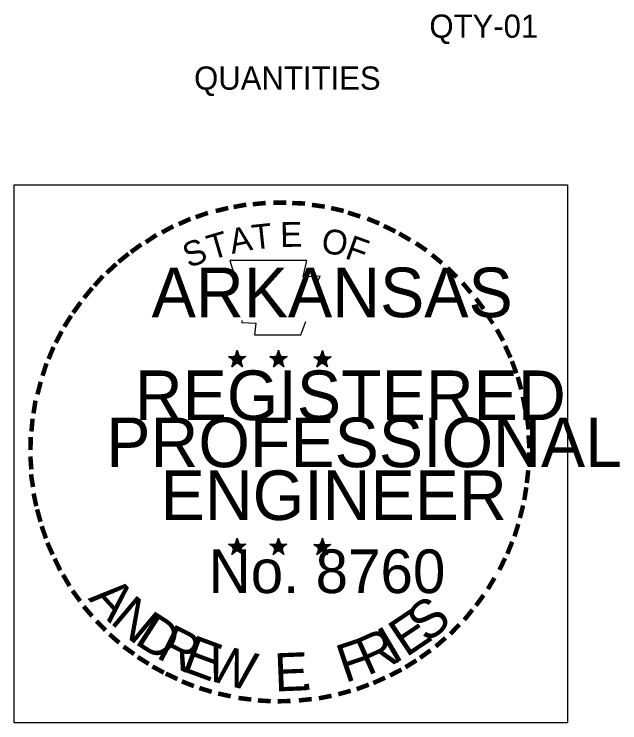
# Model space of a CAD drawing. Extents: x 1225909 to 1228704, y 151309 to 152305.
# Drawn here: x 1227979.2 to 1228131.9, y 152126.8 to 152305.5 of the extents above; entities that cross this region are included whole.
import ezdxf

# ---------------------------------------------------------------- set-up
doc = ezdxf.new("R2010")
doc.units = 0
for name, color, linetype in [('R_Border', 7, 'Continuous'), ('R_Border PE', 7, 'Continuous'), ('R_Border Prem', 7, 'Continuous')]:
    doc.layers.add(name, color=color, linetype=linetype)

msp = doc.modelspace()

# ---------------------------------------------------------------- linework, layer by layer
at = {"layer": 'R_Border PE'}
for p, q in [((1228035.41, 152220.8), (1228035.1, 152219.23)), ((1228035.41, 152220.8), (1228035.16, 152219.17)), ((1228035.41, 152220.8), (1228035.35, 152219.23)), ((1228035.41, 152218.48), (1228035.41, 152220.8)), ((1228035.41, 152220.8), (1228035.85, 152219.17)), ((1228035.41, 152220.8), (1228035.72, 152219.23)), ((1228035.41, 152220.8), (1228035.6, 152219.23)), ((1228045.85, 152220.8), (1228045.54, 152219.23)), ((1228045.85, 152220.8), (1228045.6, 152219.17)), ((1228045.85, 152220.8), (1228045.72, 152219.23)), ((1228045.85, 152218.48), (1228045.85, 152220.8)), ((1228045.85, 152220.8), (1228046.29, 152219.17)), ((1228045.85, 152220.8), (1228046.16, 152219.23)), ((1228045.85, 152220.8), (1228045.97, 152219.23)), ((1228056.91, 152220.67), (1228056.54, 152219.17)), ((1228056.91, 152220.67), (1228056.66, 152219.11)), ((1228056.91, 152220.67), (1228056.79, 152219.11)), ((1228056.91, 152218.42), (1228056.91, 152220.67)), ((1228056.91, 152220.67), (1228057.35, 152219.11)), ((1228056.91, 152220.67), (1228057.22, 152219.11)), ((1228056.91, 152220.67), (1228057.04, 152219.17)), ((1228033.22, 152219.17), (1228035.41, 152218.48)), ((1228033.22, 152219.17), (1228034.85, 152219.05)), ((1228033.22, 152219.17), (1228034.85, 152218.92)), ((1228033.22, 152219.17), (1228034.79, 152218.8)), ((1228033.22, 152219.17), (1228034.79, 152218.55)), ((1228033.22, 152219.17), (1228034.72, 152218.42)), ((1228033.22, 152219.17), (1228034.72, 152218.3)), ((1228037.6, 152219.17), (1228035.41, 152218.48)), ((1228037.6, 152219.17), (1228035.66, 152219.05)), ((1228037.6, 152219.17), (1228035.79, 152218.86)), ((1228037.6, 152219.17), (1228035.79, 152218.73)), ((1228037.6, 152219.17), (1228036.22, 152218.61)), ((1228037.6, 152219.17), (1228036.35, 152218.55)), ((1228037.6, 152219.17), (1228036.41, 152218.48)), ((1228043.66, 152219.17), (1228045.85, 152218.48)), ((1228043.66, 152219.17), (1228045.29, 152219.05)), ((1228043.66, 152219.17), (1228045.29, 152218.92)), ((1228043.66, 152219.17), (1228045.22, 152218.8)), ((1228043.66, 152219.17), (1228045.16, 152218.55)), ((1228043.66, 152219.17), (1228045.16, 152218.42)), ((1228043.66, 152219.17), (1228045.16, 152218.3)), ((1228048.04, 152219.17), (1228045.85, 152218.48)), ((1228048.04, 152219.17), (1228046.1, 152219.05)), ((1228048.04, 152219.17), (1228046.22, 152218.86)), ((1228048.04, 152219.17), (1228046.22, 152218.73)), ((1228048.04, 152219.17), (1228046.66, 152218.61)), ((1228048.04, 152219.17), (1228046.79, 152218.55)), ((1228048.04, 152219.17), (1228046.85, 152218.48)), ((1228054.72, 152219.11), (1228056.91, 152218.42)), ((1228054.72, 152219.11), (1228056.35, 152218.92)), ((1228054.72, 152219.11), (1228056.29, 152218.8)), ((1228054.72, 152219.11), (1228056.29, 152218.73)), ((1228054.72, 152219.11), (1228056.22, 152218.48)), ((1228054.72, 152219.11), (1228056.22, 152218.36)), ((1228054.72, 152219.11), (1228056.22, 152218.23)), ((1228059.1, 152219.11), (1228056.91, 152218.42)), ((1228059.1, 152219.11), (1228057.16, 152218.98)), ((1228059.1, 152219.11), (1228057.29, 152218.8)), ((1228059.1, 152219.11), (1228057.29, 152218.67)), ((1228059.1, 152219.11), (1228057.72, 152218.55)), ((1228059.1, 152219.11), (1228057.79, 152218.48)), ((1228059.1, 152219.11), (1228057.91, 152218.42)), ((1228034.1, 152216.61), (1228035.41, 152218.48)), ((1228034.1, 152216.61), (1228034.79, 152218.36)), ((1228034.1, 152216.61), (1228034.85, 152218.17)), ((1228034.1, 152216.61), (1228034.97, 152218.11)), ((1228034.1, 152216.61), (1228035.41, 152217.98)), ((1228034.1, 152216.61), (1228035.16, 152217.92)), ((1228034.1, 152216.61), (1228035.47, 152217.8)), ((1228036.79, 152216.61), (1228035.41, 152218.48)), ((1228036.79, 152216.61), (1228035.41, 152217.98)), ((1228036.79, 152216.61), (1228035.41, 152217.8)), ((1228036.79, 152216.61), (1228035.66, 152217.92)), ((1228036.79, 152216.61), (1228035.85, 152218.17)), ((1228036.79, 152216.61), (1228035.91, 152218.42)), ((1228036.79, 152216.61), (1228036.04, 152218.48)), ((1228044.54, 152216.61), (1228045.85, 152218.48)), ((1228044.54, 152216.61), (1228045.22, 152218.36)), ((1228044.54, 152216.61), (1228045.29, 152218.17)), ((1228044.54, 152216.61), (1228045.41, 152218.11)), ((1228044.54, 152216.61), (1228045.85, 152217.98)), ((1228044.54, 152216.61), (1228045.6, 152217.92)), ((1228044.54, 152216.61), (1228045.91, 152217.8)), ((1228047.22, 152216.61), (1228045.85, 152218.48)), ((1228047.22, 152216.61), (1228045.85, 152217.98)), ((1228047.22, 152216.61), (1228045.85, 152217.8)), ((1228047.22, 152216.61), (1228046.1, 152217.92)), ((1228047.22, 152216.61), (1228046.29, 152218.17)), ((1228047.22, 152216.61), (1228046.35, 152218.42)), ((1228047.22, 152216.61), (1228046.47, 152218.48)), ((1228055.54, 152216.55), (1228056.91, 152218.42)), ((1228055.54, 152216.55), (1228056.29, 152218.3)), ((1228055.54, 152216.55), (1228056.35, 152218.11)), ((1228055.54, 152216.55), (1228056.47, 152218.05)), ((1228055.54, 152216.55), (1228056.91, 152217.92)), ((1228055.54, 152216.55), (1228056.66, 152217.86)), ((1228055.54, 152216.55), (1228056.97, 152217.73)), ((1228058.22, 152216.55), (1228056.91, 152218.42)), ((1228058.22, 152216.55), (1228056.91, 152217.92)), ((1228058.22, 152216.55), (1228056.91, 152217.73)), ((1228058.22, 152216.55), (1228057.16, 152217.86)), ((1228058.22, 152216.55), (1228057.35, 152218.11)), ((1228058.22, 152216.55), (1228057.41, 152218.36)), ((1228058.22, 152216.55), (1228057.54, 152218.36)), ((1228035.41, 152173.42), (1228035.04, 152171.92)), ((1228035.41, 152173.42), (1228035.16, 152171.86)), ((1228035.41, 152173.42), (1228035.29, 152171.86)), ((1228035.41, 152171.17), (1228035.41, 152173.42)), ((1228035.41, 152173.42), (1228035.85, 152171.86)), ((1228035.41, 152173.42), (1228035.72, 152171.86)), ((1228035.41, 152173.42), (1228035.54, 152171.86)), ((1228045.85, 152173.42), (1228045.47, 152171.92)), ((1228045.85, 152173.42), (1228045.6, 152171.86)), ((1228045.85, 152173.42), (1228045.72, 152171.86)), ((1228045.85, 152171.17), (1228045.85, 152173.42)), ((1228045.85, 152173.42), (1228046.22, 152171.86)), ((1228045.85, 152173.42), (1228046.16, 152171.86)), ((1228045.85, 152173.42), (1228045.97, 152171.86)), ((1228056.91, 152173.36), (1228056.54, 152171.8)), ((1228056.91, 152173.36), (1228056.66, 152171.8)), ((1228056.91, 152173.36), (1228056.79, 152171.8)), ((1228056.91, 152171.11), (1228056.91, 152173.36)), ((1228056.91, 152173.36), (1228057.29, 152171.8)), ((1228056.91, 152173.36), (1228057.22, 152171.8)), ((1228056.91, 152173.36), (1228057.04, 152171.8)), ((1228033.22, 152171.86), (1228035.41, 152171.17)), ((1228033.22, 152171.86), (1228034.85, 152171.67)), ((1228033.22, 152171.86), (1228034.79, 152171.55)), ((1228033.22, 152171.86), (1228034.79, 152171.48)), ((1228033.22, 152171.86), (1228034.72, 152171.23)), ((1228033.22, 152171.86), (1228034.72, 152171.11)), ((1228033.22, 152171.86), (1228034.72, 152170.98)), ((1228034.04, 152169.3), (1228035.41, 152171.17)), ((1228034.04, 152169.3), (1228034.79, 152171.05)), ((1228034.04, 152169.3), (1228034.85, 152170.8)), ((1228034.04, 152169.3), (1228034.97, 152170.73)), ((1228034.04, 152169.3), (1228035.41, 152170.67)), ((1228034.04, 152169.3), (1228035.16, 152170.61)), ((1228034.04, 152169.3), (1228035.41, 152170.48)), ((1228036.72, 152169.3), (1228035.35, 152170.48)), ((1228037.6, 152171.86), (1228035.41, 152171.17)), ((1228036.72, 152169.3), (1228035.41, 152171.17)), ((1228036.72, 152169.3), (1228035.41, 152170.61)), ((1228036.72, 152169.3), (1228035.6, 152170.61)), ((1228037.6, 152171.86), (1228035.66, 152171.73)), ((1228037.6, 152171.86), (1228035.79, 152171.55)), ((1228037.6, 152171.86), (1228035.79, 152171.42)), ((1228036.72, 152169.3), (1228035.85, 152171.11)), ((1228036.72, 152169.3), (1228035.85, 152170.86)), ((1228036.72, 152169.3), (1228036.04, 152171.11)), ((1228037.6, 152171.86), (1228036.16, 152171.3)), ((1228037.6, 152171.86), (1228036.29, 152171.23)), ((1228037.6, 152171.86), (1228036.41, 152171.11)), ((1228043.66, 152171.86), (1228045.85, 152171.17)), ((1228043.66, 152171.86), (1228045.22, 152171.67)), ((1228043.66, 152171.86), (1228045.22, 152171.55)), ((1228043.66, 152171.86), (1228045.22, 152171.48)), ((1228043.66, 152171.86), (1228045.16, 152171.23)), ((1228043.66, 152171.86), (1228045.16, 152171.11)), ((1228043.66, 152171.86), (1228045.16, 152170.98)), ((1228044.47, 152169.3), (1228045.85, 152171.17)), ((1228044.47, 152169.3), (1228045.22, 152171.05)), ((1228044.47, 152169.3), (1228045.29, 152170.8)), ((1228044.47, 152169.3), (1228045.41, 152170.73)), ((1228044.47, 152169.3), (1228045.85, 152170.67)), ((1228044.47, 152169.3), (1228045.6, 152170.61)), ((1228044.47, 152169.3), (1228045.85, 152170.48)), ((1228047.16, 152169.3), (1228045.79, 152170.48)), ((1228047.97, 152171.86), (1228045.85, 152171.17)), ((1228047.16, 152169.3), (1228045.85, 152171.17)), ((1228047.16, 152169.3), (1228045.85, 152170.61)), ((1228047.16, 152169.3), (1228046.04, 152170.61)), ((1228047.97, 152171.86), (1228046.1, 152171.73)), ((1228047.97, 152171.86), (1228046.22, 152171.55)), ((1228047.97, 152171.86), (1228046.22, 152171.42)), ((1228047.16, 152169.3), (1228046.29, 152171.11)), ((1228047.16, 152169.3), (1228046.29, 152170.86)), ((1228047.16, 152169.3), (1228046.47, 152171.11)), ((1228047.97, 152171.86), (1228046.6, 152171.3)), ((1228047.97, 152171.86), (1228046.72, 152171.23)), ((1228047.97, 152171.86), (1228046.85, 152171.11)), ((1228054.72, 152171.8), (1228056.91, 152171.11)), ((1228054.72, 152171.8), (1228056.29, 152171.61)), ((1228054.72, 152171.8), (1228056.29, 152171.48)), ((1228054.72, 152171.8), (1228056.22, 152171.36)), ((1228054.72, 152171.8), (1228056.22, 152171.17)), ((1228054.72, 152171.8), (1228056.16, 152170.98)), ((1228054.72, 152171.8), (1228056.16, 152170.86)), ((1228055.54, 152169.23), (1228056.91, 152171.11)), ((1228055.54, 152169.23), (1228056.22, 152170.98)), ((1228055.54, 152169.23), (1228056.29, 152170.73)), ((1228055.54, 152169.23), (1228056.47, 152170.67)), ((1228055.54, 152169.23), (1228056.66, 152170.55)), ((1228055.54, 152169.23), (1228056.85, 152170.55)), ((1228058.22, 152169.23), (1228056.85, 152170.55)), ((1228059.04, 152171.8), (1228056.91, 152171.11)), ((1228058.22, 152169.23), (1228056.91, 152171.11)), ((1228058.22, 152169.23), (1228057.1, 152170.55)), ((1228059.04, 152171.8), (1228057.16, 152171.67)), ((1228059.04, 152171.8), (1228057.29, 152171.48)), ((1228059.04, 152171.8), (1228057.29, 152171.36)), ((1228058.22, 152169.23), (1228057.29, 152170.73)), ((1228058.22, 152169.23), (1228057.35, 152171.05)), ((1228058.22, 152169.23), (1228057.47, 152171.05)), ((1228059.04, 152171.8), (1228057.66, 152171.23)), ((1228059.04, 152171.8), (1228057.79, 152171.11)), ((1228059.04, 152171.8), (1228057.85, 152171.05)), ((1228055.54, 152169.23), (1228056.91, 152170.42)), ((1228058.22, 152169.23), (1228056.85, 152170.36))]:
    msp.add_line(p, q, dxfattribs=at)
for points in [[(1228033.54, 152243.42), (1228035.16, 152238.23)], [(1228055.47, 152237.67), (1228056.35, 152239.42), (1228052.04, 152239.3), (1228052.97, 152243.42), (1228033.54, 152243.42)], [(1228036.6, 152228.3), (1228036.6, 152227.73), (1228040.1, 152227.61), (1228039.79, 152224.67), (1228051.47, 152224.67), (1228052.72, 152227.98)], [(1228035.41, 152220.8), (1228036.79, 152216.61), (1228033.22, 152219.17), (1228037.6, 152219.17), (1228034.1, 152216.61), (1228035.41, 152220.8)], [(1228045.85, 152220.8), (1228047.22, 152216.61), (1228043.66, 152219.17), (1228048.04, 152219.17), (1228044.54, 152216.61), (1228045.85, 152220.8)], [(1228056.91, 152220.67), (1228058.22, 152216.55), (1228054.72, 152219.11), (1228059.1, 152219.11), (1228055.54, 152216.55), (1228056.91, 152220.67)], [(1228035.41, 152173.42), (1228036.72, 152169.3), (1228033.22, 152171.86), (1228037.6, 152171.86), (1228034.04, 152169.3), (1228035.41, 152173.42)], [(1228045.85, 152173.42), (1228047.16, 152169.3), (1228043.66, 152171.86), (1228047.97, 152171.86), (1228044.47, 152169.3), (1228045.85, 152173.42)], [(1228056.91, 152173.36), (1228058.22, 152169.23), (1228054.72, 152171.8), (1228059.04, 152171.8), (1228055.54, 152169.23), (1228056.91, 152173.36)]]:
    msp.add_lwpolyline(points, dxfattribs=at)
for centre, radius in [((1228035.43, 152218.48), 1.08), ((1228035.43, 152218.48), 0.975), ((1228035.43, 152218.48), 0.904), ((1228035.43, 152218.48), 0.83), ((1228035.43, 152218.48), 0.723), ((1228035.43, 152218.48), 0.672), ((1228035.43, 152218.48), 0.619), ((1228035.43, 152218.48), 0.533), ((1228035.43, 152218.48), 0.467), ((1228035.43, 152218.48), 0.388), ((1228035.43, 152218.48), 0.31), ((1228035.43, 152218.48), 0.231), ((1228045.86, 152218.48), 1.08), ((1228045.86, 152218.48), 0.975), ((1228045.86, 152218.48), 0.904), ((1228045.86, 152218.48), 0.83), ((1228045.86, 152218.48), 0.723), ((1228045.86, 152218.48), 0.672), ((1228045.86, 152218.48), 0.619), ((1228045.86, 152218.48), 0.533), ((1228045.86, 152218.48), 0.467), ((1228045.86, 152218.48), 0.388), ((1228045.86, 152218.48), 0.31), ((1228045.86, 152218.48), 0.231), ((1228056.91, 152218.41), 1.08), ((1228056.91, 152218.41), 0.975), ((1228056.91, 152218.41), 0.904), ((1228056.91, 152218.41), 0.83), ((1228056.91, 152218.41), 0.723), ((1228056.91, 152218.41), 0.672), ((1228056.91, 152218.41), 0.619), ((1228056.91, 152218.41), 0.533), ((1228056.91, 152218.41), 0.467), ((1228056.91, 152218.41), 0.388), ((1228056.91, 152218.41), 0.31), ((1228035.43, 152218.48), 0.185), ((1228035.43, 152218.48), 0.0901), ((1228045.86, 152218.48), 0.185), ((1228045.86, 152218.48), 0.0901), ((1228056.91, 152218.41), 0.231), ((1228056.91, 152218.41), 0.185), ((1228056.91, 152218.41), 0.0901), ((1228035.4, 152171.15), 1.08), ((1228035.4, 152171.15), 0.975), ((1228035.4, 152171.15), 0.904), ((1228035.4, 152171.15), 0.83), ((1228035.4, 152171.15), 0.723), ((1228035.4, 152171.15), 0.672), ((1228035.4, 152171.15), 0.619), ((1228035.4, 152171.15), 0.533), ((1228035.4, 152171.15), 0.467), ((1228035.4, 152171.15), 0.388), ((1228035.4, 152171.15), 0.31), ((1228035.4, 152171.15), 0.231), ((1228035.4, 152171.15), 0.185), ((1228035.4, 152171.15), 0.0901), ((1228045.84, 152171.15), 1.08), ((1228045.84, 152171.15), 0.975), ((1228045.84, 152171.15), 0.904), ((1228045.84, 152171.15), 0.83), ((1228045.84, 152171.15), 0.723), ((1228045.84, 152171.15), 0.672), ((1228045.84, 152171.15), 0.619), ((1228045.84, 152171.15), 0.533), ((1228045.84, 152171.15), 0.467), ((1228045.84, 152171.15), 0.388), ((1228045.84, 152171.15), 0.31), ((1228045.84, 152171.15), 0.231), ((1228045.84, 152171.15), 0.185), ((1228045.84, 152171.15), 0.0901), ((1228056.88, 152171.08), 1.08), ((1228056.88, 152171.08), 0.975), ((1228056.88, 152171.08), 0.904), ((1228056.88, 152171.08), 0.83), ((1228056.88, 152171.08), 0.723), ((1228056.88, 152171.08), 0.672), ((1228056.88, 152171.08), 0.619), ((1228056.88, 152171.08), 0.533), ((1228056.88, 152171.08), 0.467), ((1228056.88, 152171.08), 0.388), ((1228056.88, 152171.08), 0.31), ((1228056.88, 152171.08), 0.231), ((1228056.88, 152171.08), 0.185), ((1228056.88, 152171.08), 0.0901)]:
    msp.add_circle(centre, radius, dxfattribs=at)
at = {"layer": 'R_Border Prem'}
msp.add_lwpolyline([(1227979.19, 152262.47), (1228118.69, 152262.47), (1228118.69, 152126.85), (1227979.19, 152126.85)], close=True, dxfattribs=at)

# ---------------------------------------------------------------- texts
at = {"layer": 'R_Border'}
for s, height, p in [('QTY-01', 5.861, (1228083.88, 152299.55)), ('QUANTITIES', 5.862, (1228024.56, 152286.45))]:
    msp.add_text(s, height=height, dxfattribs=at).set_placement(p)
at = {"layer": 'R_Border PE'}
for s, height, rotation, p in [('-', 10, 10.2193, (1228034.6, 152252.98)), ('-', 10, 5.8968, (1228039.16, 152253.67)), ('-', 10, 0.1862, (1228043.97, 152254.11)), ('-', 10, 357.743, (1228048.54, 152254.05)), ('-', 10, 13.6302, (1228030.35, 152251.98)), ('-', 10, 352.1617, (1228053.16, 152253.67)), ('-', 10, 347.2049, (1228057.66, 152252.98)), ('-', 10, 24.3072, (1228021.72, 152248.8)), ('-', 10, 19.1761, (1228025.66, 152250.48)), ('-', 10, 342.3362, (1228061.6, 152251.98)), ('-', 10, 337.8551, (1228066.22, 152250.61)), ('T', 6.25, 6.0228, (1228039.41, 152246.11)), ('E', 6.25, 0.8323, (1228046.29, 152246.8)), ('-', 10, 334.1211, (1228070.16, 152248.92)), ('-', 10, 28.7918, (1228017.79, 152246.8)), ('T', 6.25, 16.4036, (1228028.91, 152243.48)), ('A', 6.25, 11.2132, (1228034.1, 152245.05)), ('O', 6.25, 350.4515, (1228056.35, 152245.48)), ('-', 10, 34.0636, (1228014.04, 152244.48)), ('F', 6.25, 340.0707, (1228062.29, 152244.05)), ('-', 10, 329.6409, (1228073.79, 152247.17)), ('-', 10, 36.2317, (1228010.41, 152242.05)), ('S', 6.25, 21.594, (1228023.22, 152241.42)), ('-', 10, 325.8627, (1228077.79, 152244.92)), ('-', 10, 38.9507, (1228007.47, 152239.67)), ('-', 10, 320.5297, (1228081.6, 152242.23)), ('-', 10, 42.9622, (1228004.72, 152237.05)), ('-', 10, 315.5786, (1228085.35, 152239.17)), ('-', 10, 48.423, (1228001.91, 152234.05)), ('-', 10, 50.6142, (1227999.41, 152231.05)), ('-', 10, 309.8797, (1228088.91, 152235.73)), ('-', 10, 54.2325, (1227996.85, 152227.48)), ('-', 10, 306.6522, (1228092.16, 152231.98)), ('-', 10, 58.0706, (1227994.79, 152224.17)), ('-', 8.75, 303.6753, (1228095.22, 152228.42)), ('-', 10, 299.6684, (1228097.22, 152224.61)), ('-', 10, 62.8713, (1227992.85, 152220.36)), ('-', 10, 67.7743, (1227991.22, 152216.55)), ('-', 10, 294.6628, (1228099.22, 152220.8)), ('-', 10, 72.3945, (1227989.85, 152212.61)), ('-', 10, 290.5728, (1228100.85, 152217.23)), ('-', 10, 285.1233, (1228102.29, 152213.61)), ('-', 10, 75.461, (1227988.66, 152208.11)), ('-', 10, 81.2013, (1227987.79, 152203.67)), ('-', 10, 280.5493, (1228103.54, 152208.92)), ('-', 10, 85.1863, (1227987.35, 152199.36)), ('-', 10, 276.5962, (1228104.6, 152204.17)), ('-', 10, 274.3301, (1228104.97, 152199.61)), ('-', 10, 89.0622, (1227987.16, 152194.98)), ('-', 10, 94.1959, (1227987.41, 152190.42)), ('-', 10, 269.9407, (1228105.16, 152195.67)), ('-', 10, 263.5172, (1228105.04, 152191.55)), ('-', 10, 98.9479, (1227987.85, 152186.3)), ('-', 10, 101.7149, (1227988.66, 152181.67)), ('-', 10, 260.9953, (1228104.6, 152187.42)), ('-', 10, 255.7626, (1228103.91, 152183.17)), ('-', 10, 105.4578, (1227989.72, 152177.98)), ('-', 10, 109.0874, (1227991.04, 152174.05)), ('-', 10, 252.8681, (1228102.79, 152178.67)), ('-', 10, 114.0643, (1227992.66, 152170.3)), ('-', 10, 247.8887, (1228101.41, 152174.48)), ('-', 10, 115.7289, (1227994.54, 152166.42)), ('-', 10, 244.6197, (1228099.72, 152170.55)), ('-', 10, 120.4471, (1227996.79, 152162.8)), ('-', 10, 239.0712, (1228097.29, 152165.86)), ('A', 9.62, 312.4727, (1227997.66, 152158.1)), ('-', 10, 125.8934, (1227999.29, 152159.3)), ('N', 9.62, 319.8362, (1228003.09, 152152.17)), ('S', 9.62, 39.723, (1228083.33, 152146.71)), ('-', 10, 233.8452, (1228094.79, 152161.8)), ('-', 10, 130.7181, (1228002.16, 152155.8)), ('D', 9.62, 327.1996, (1228009.24, 152146.98)), ('E', 9.62, 33.8878, (1228077.99, 152143.22)), ('-', 10, 231.2538, (1228092.1, 152158.23)), ('-', 10, 134.2238, (1228005.41, 152152.42)), ('R', 9.62, 333.1738, (1228014.68, 152143.38)), ('I', 9.62, 30.5534, (1228074.79, 152141.48)), ('-', 10, 225.7653, (1228089.1, 152154.73)), ('-', 10, 138.9338, (1228008.66, 152149.55)), ('R', 9.62, 24.0235, (1228068.25, 152138.62)), ('E', 9.62, 339.7037, (1228021.03, 152140.12)), ('F', 9.62, 18.6051, (1228062.61, 152136.83)), ('-', 10, 221.0851, (1228085.85, 152151.55)), ('-', 10, 144.6463, (1228012.16, 152146.98)), ('W', 9.62, 345.5389, (1228026.98, 152137.83)), ('-', 10, 215.7363, (1228082.41, 152148.61)), ('-', 10, 148.0898, (1228015.66, 152144.67)), ('E', 9.62, 2.2804, (1228044.95, 152134.73)), ('-', 10, 212.2491, (1228079.04, 152146.17)), ('-', 10, 151.5704, (1228019.29, 152142.61)), ('-', 10, 207.3568, (1228075.6, 152143.98)), ('-', 10, 154.6002, (1228022.54, 152141.11)), ('-', 10, 204.2516, (1228071.66, 152141.98)), ('-', 10, 158.5612, (1228026.47, 152139.48)), ('.', 9.62, 8.1156, (1228051.32, 152134.9)), ('-', 10, 200.7184, (1228067.79, 152140.3)), ('-', 10, 162.7983, (1228030.72, 152138.17)), ('-', 10, 167.5555, (1228035.22, 152137.17)), ('-', 10, 195.4743, (1228063.6, 152138.8)), ('-', 10, 173.1155, (1228040.04, 152136.48)), ('-', 10, 176.5183, (1228044.72, 152136.11)), ('-', 10, 185.8167, (1228054.41, 152136.73)), ('-', 10, 191.2858, (1228059.04, 152137.55)), ('-', 10, 181.5918, (1228049.35, 152136.23))]:
    msp.add_text(s, height=height, rotation=rotation, dxfattribs=at).set_placement(p)
for s, height, p in [('ARKANSAS', 12.5, (1228013.85, 152229.11)), ('REGISTERED', 12.5, (1228009.6, 152203.17)), ('PROFESSIONAL', 12.4999, (1228002.41, 152191.3)), ('ENGINEER', 12.5, (1228016.1, 152177.98)), ('No. 8760', 11, (1228028.21, 152159.55))]:
    msp.add_text(s, height=height, dxfattribs=at).set_placement(p)

doc.saveas('drawing.dxf')
